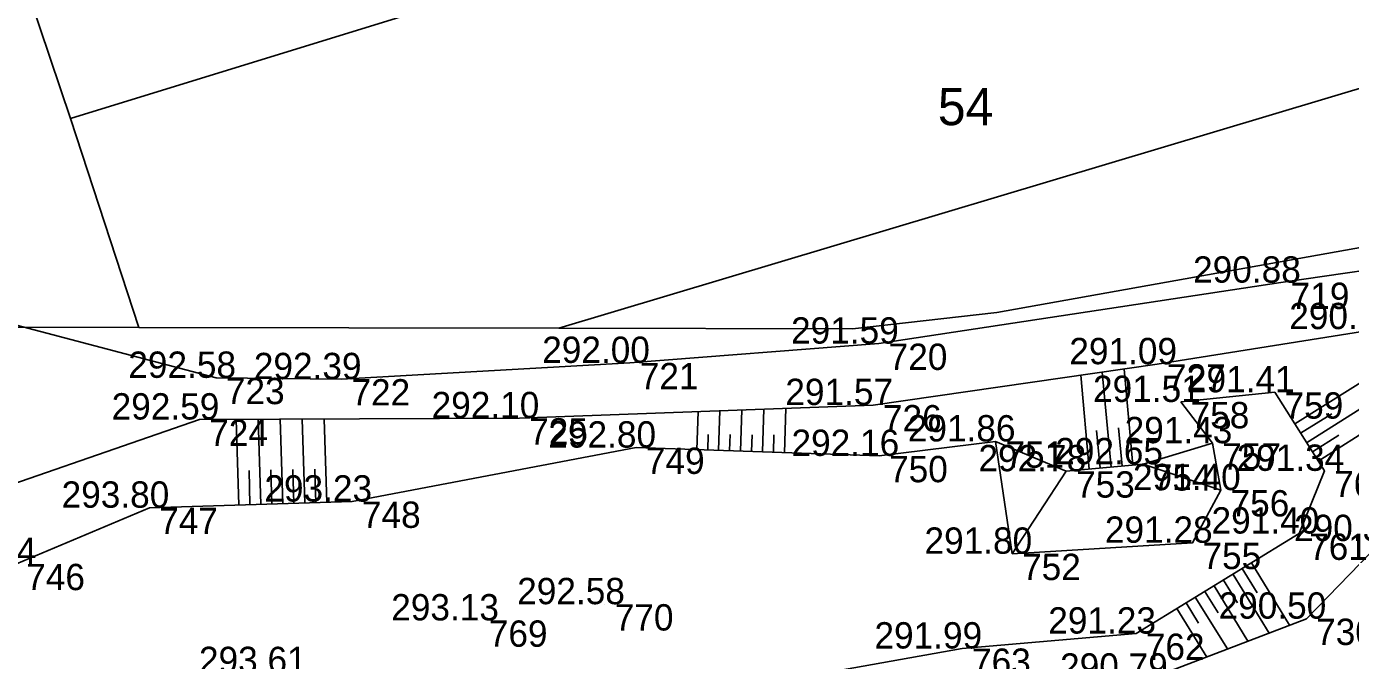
# Model space of a CAD drawing. Extents: x -599970 to -599524, y -1154772 to -1154457.
# Drawn here: x -599732.99 to -599702.82, y -1154607.5 to -1154593.05 of the extents above; entities that cross this region are included whole.
import ezdxf

# ---------------------------------------------------------------- set-up
doc = ezdxf.new("R2010")
doc.units = 0
for name, color, linetype in [('Z-KATASTRALNI MAPA', 7, 'Continuous'), ('Z-PLOT DRATENY', 7, 'Continuous'), ('Z-PODROBNE BODY', 7, 'Continuous'), ('Z-PODROBNE BODY-CISLO', 7, 'Continuous'), ('Z-PODROBNE BODY-VYSKA', 7, 'Continuous'), ('Z-SRAFOVANI SVAHU', 7, 'Continuous'), ('Z-TERENNI HRANY PATY', 7, 'Continuous')]:
    doc.layers.add(name, color=color, linetype=linetype)

msp = doc.modelspace()

# ---------------------------------------------------------------- linework, layer by layer
at = {"layer": 'Z-KATASTRALNI MAPA'}
for p, q in [((-599696.79, -1154584.29), (-599731.99, -1154595.15)), ((-599731.99, -1154595.15), (-599733.83, -1154589.64)), ((-599694.67, -1154592.08), (-599720.86, -1154599.93)), ((-599730.43, -1154599.91), (-599731.99, -1154595.15)), ((-599720.86, -1154599.93), (-599730.43, -1154599.91))]:
    msp.add_line(p, q, dxfattribs=at)
for points in [[(-599693.47, -1154596.46), (-599697.17, -1154597.32), (-599702, -1154597.98), (-599710.88, -1154599.57), (-599714.17, -1154599.94), (-599720.86, -1154599.93)], [(-599730.43, -1154599.91), (-599736.76, -1154599.9), (-599740.19, -1154600.9), (-599741.29, -1154597.51)]]:
    msp.add_lwpolyline(points, dxfattribs=at)
at = {"layer": 'Z-PLOT DRATENY'}
msp.add_lwpolyline([(-599741.2, -1154597.57), (-599735.3, -1154599.31), (-599728.67, -1154601.06), (-599725.81, -1154601.09), (-599719.24, -1154600.72), (-599713.57, -1154600.28), (-599704.41, -1154598.89), (-599697.5, -1154597.88)], dxfattribs=at)
at = {"layer": 'Z-PODROBNE BODY'}
for p, q in [((-599704.41, -1154598.89), (-599704.41, -1154598.89)), ((-599713.57, -1154600.28), (-599713.57, -1154600.28)), ((-599719.24, -1154600.72), (-599719.24, -1154600.72)), ((-599707.23, -1154600.75), (-599707.23, -1154600.75)), ((-599728.67, -1154601.06), (-599728.67, -1154601.06)), ((-599725.81, -1154601.09), (-599725.81, -1154601.09)), ((-599704.55, -1154601.39), (-599704.55, -1154601.39)), ((-599713.7, -1154601.68), (-599713.7, -1154601.68)), ((-599706.69, -1154601.61), (-599706.69, -1154601.61)), ((-599729.05, -1154602.01), (-599729.05, -1154602.01)), ((-599721.76, -1154601.98), (-599721.76, -1154601.98)), ((-599719.1, -1154602.65), (-599719.1, -1154602.65)), ((-599710.91, -1154602.51), (-599710.91, -1154602.51)), ((-599705.97, -1154602.55), (-599705.97, -1154602.55)), ((-599713.56, -1154602.84), (-599713.56, -1154602.84)), ((-599707.55, -1154603.03), (-599707.55, -1154603.03)), ((-599709.3, -1154603.19), (-599709.3, -1154603.19)), ((-599703.42, -1154603.18), (-599703.42, -1154603.18)), ((-599705.78, -1154603.62), (-599705.78, -1154603.62)), ((-599725.57, -1154603.88), (-599725.57, -1154603.88)), ((-599730.19, -1154604.02), (-599730.19, -1154604.02)), ((-599706.42, -1154604.82), (-599706.42, -1154604.82)), ((-599703.99, -1154604.61), (-599703.99, -1154604.61)), ((-599710.53, -1154605.07), (-599710.53, -1154605.07)), ((-599719.81, -1154606.22), (-599719.81, -1154606.22)), ((-599722.68, -1154606.59), (-599722.68, -1154606.59)), ((-599703.83, -1154606.55), (-599703.83, -1154606.55)), ((-599707.71, -1154606.89), (-599707.71, -1154606.89)), ((-599711.67, -1154607.23), (-599711.67, -1154607.23))]:
    msp.add_line(p, q, dxfattribs=at)
at = {"layer": 'Z-SRAFOVANI SVAHU'}
for points in [[(-599708.28, -1154603.1), (-599708.48, -1154600.93)], [(-599707.78, -1154603.05), (-599707.98, -1154600.86)], [(-599704.09, -1154602.11), (-599702.2, -1154600.92)], [(-599708.78, -1154603.14), (-599708.97, -1154601)], [(-599703.83, -1154602.54), (-599702.18, -1154601.5)], [(-599717.72, -1154602.7), (-599717.69, -1154601.83)], [(-599717.22, -1154602.71), (-599717.19, -1154601.81)], [(-599716.72, -1154602.73), (-599716.69, -1154601.79)], [(-599716.22, -1154602.75), (-599716.19, -1154601.77)], [(-599715.72, -1154602.77), (-599715.69, -1154601.75)], [(-599703.96, -1154602.32), (-599703.25, -1154601.88)], [(-599728.15, -1154603.96), (-599728.21, -1154602.01)], [(-599727.65, -1154603.94), (-599727.71, -1154602)], [(-599727.15, -1154603.93), (-599727.21, -1154602)], [(-599726.65, -1154603.91), (-599726.71, -1154602)], [(-599726.15, -1154603.9), (-599726.21, -1154602)], [(-599703.56, -1154602.96), (-599702.17, -1154602.08)], [(-599717.47, -1154602.71), (-599717.46, -1154602.35)], [(-599716.97, -1154602.72), (-599716.96, -1154602.35)], [(-599716.47, -1154602.74), (-599716.46, -1154602.36)], [(-599715.97, -1154602.76), (-599715.96, -1154602.36)], [(-599708.53, -1154603.12), (-599708.61, -1154602.26)], [(-599708.03, -1154603.07), (-599708.11, -1154602.2)], [(-599703.69, -1154602.75), (-599703.09, -1154602.37)], [(-599727.9, -1154603.95), (-599727.92, -1154603.17)], [(-599727.4, -1154603.94), (-599727.42, -1154603.16)], [(-599726.9, -1154603.92), (-599726.92, -1154603.15)], [(-599726.4, -1154603.91), (-599726.42, -1154603.14)], [(-599705.29, -1154605.41), (-599704.95, -1154605.96)], [(-599705.08, -1154605.28), (-599704.21, -1154606.7)], [(-599705.93, -1154605.8), (-599705.16, -1154607.06)], [(-599705.72, -1154605.67), (-599705.4, -1154606.19)], [(-599705.5, -1154605.54), (-599704.68, -1154606.88)], [(-599706.36, -1154606.06), (-599705.63, -1154607.24)], [(-599706.14, -1154605.93), (-599705.84, -1154606.42)], [(-599706.78, -1154606.32), (-599706.1, -1154607.43)], [(-599706.57, -1154606.19), (-599706.29, -1154606.65)]]:
    msp.add_lwpolyline(points, dxfattribs=at)
at = {"layer": 'Z-TERENNI HRANY PATY'}
for points in [[(-599729.05, -1154602.01), (-599721.76, -1154601.98), (-599713.7, -1154601.68), (-599707.23, -1154600.75), (-599702.22, -1154599.95), (-599702.11, -1154604.78), (-599703.83, -1154606.55), (-599707.44, -1154607.94), (-599715.66, -1154610.06), (-599723.72, -1154611.89), (-599730.02, -1154613.49), (-599734.59, -1154613.85), (-599735.4, -1154613.47), (-599737.38, -1154610.51), (-599738.93, -1154607.87), (-599737.97, -1154605.84), (-599735.06, -1154604.09), (-599729.05, -1154602.01)], [(-599706.69, -1154601.61), (-599704.55, -1154601.39), (-599703.42, -1154603.18), (-599703.99, -1154604.61), (-599707.71, -1154606.89), (-599711.67, -1154607.23), (-599718.57, -1154608.46), (-599724.85, -1154610.8), (-599730.76, -1154612.67), (-599734.46, -1154612.65)], [(-599710.91, -1154602.51), (-599710.53, -1154605.07), (-599706.42, -1154604.82), (-599705.78, -1154603.62), (-599705.97, -1154602.55), (-599706.69, -1154601.61)], [(-599734.46, -1154612.65), (-599734.67, -1154611.2), (-599735.18, -1154609.79), (-599737.16, -1154608.3), (-599736.95, -1154607.23), (-599733.22, -1154605.3), (-599730.19, -1154604.02), (-599725.57, -1154603.88), (-599719.1, -1154602.65), (-599713.56, -1154602.84), (-599710.91, -1154602.51)], [(-599710.91, -1154602.51), (-599709.3, -1154603.19), (-599710.53, -1154605.07)], [(-599705.97, -1154602.55), (-599707.55, -1154603.03), (-599705.78, -1154603.62)], [(-599709.3, -1154603.19), (-599707.55, -1154603.03)]]:
    msp.add_lwpolyline(points, dxfattribs=at)

# ---------------------------------------------------------------- texts
at = {"layer": 'Z-KATASTRALNI MAPA'}
msp.add_text('54', height=0.85, dxfattribs=at).set_placement((-599712.226, -1154595.3))
at = {"layer": 'Z-PODROBNE BODY-CISLO'}
for s, p in [(' 719', (-599704.41, -1154599.49)), (' 720', (-599713.57, -1154600.88)), (' 721', (-599719.24, -1154601.32)), (' 727', (-599707.23, -1154601.35)), (' 723', (-599728.67, -1154601.66)), (' 722', (-599725.81, -1154601.69)), (' 759', (-599704.55, -1154601.99)), (' 726', (-599713.7, -1154602.28)), (' 758', (-599706.69, -1154602.21)), (' 724', (-599729.05, -1154602.61)), (' 725', (-599721.76, -1154602.58)), (' 749', (-599719.1, -1154603.25)), (' 751', (-599710.91, -1154603.11)), (' 757', (-599705.97, -1154603.15)), (' 750', (-599713.56, -1154603.44)), (' 754', (-599707.55, -1154603.63)), (' 753', (-599709.3, -1154603.79)), (' 760', (-599703.42, -1154603.78)), (' 756', (-599705.78, -1154604.22)), (' 748', (-599725.57, -1154604.48)), (' 747', (-599730.19, -1154604.62)), (' 761', (-599703.99, -1154605.21)), (' 755', (-599706.42, -1154605.42)), (' 752', (-599710.53, -1154605.67)), (' 746', (-599733.22, -1154605.9)), (' 770', (-599719.81, -1154606.82)), (' 769', (-599722.68, -1154607.19)), (' 730', (-599703.83, -1154607.15)), (' 762', (-599707.71, -1154607.49)), (' 763', (-599711.67, -1154607.83))]:
    msp.add_text(s, height=0.6, dxfattribs=at).set_placement(p)
at = {"layer": 'Z-PODROBNE BODY-VYSKA'}
for s, p in [('290.88 ', (-599706.41, -1154598.89)), ('290.65 ', (-599704.22, -1154599.95)), ('291.59 ', (-599715.57, -1154600.28)), ('292.00 ', (-599721.24, -1154600.72)), ('291.09 ', (-599709.23, -1154600.75)), ('292.58 ', (-599730.67, -1154601.06)), ('292.39 ', (-599727.81, -1154601.09)), ('291.41 ', (-599706.55, -1154601.39)), ('291.57 ', (-599715.7, -1154601.68)), ('291.51 ', (-599708.69, -1154601.61)), ('292.59 ', (-599731.05, -1154602.01)), ('292.10 ', (-599723.76, -1154601.98)), ('292.80 ', (-599721.1, -1154602.65)), ('291.86 ', (-599712.91, -1154602.51)), ('291.43 ', (-599707.97, -1154602.55)), ('292.16 ', (-599715.56, -1154602.84)), ('292.65 ', (-599709.55, -1154603.03)), ('292.78 ', (-599711.3, -1154603.19)), ('291.34 ', (-599705.42, -1154603.18)), ('291.40 ', (-599707.78, -1154603.62)), ('293.23 ', (-599727.57, -1154603.88)), ('293.80 ', (-599732.19, -1154604.02)), ('291.28 ', (-599708.42, -1154604.82)), ('291.40 ', (-599705.99, -1154604.61)), ('290.37 ', (-599704.11, -1154604.78)), ('291.80 ', (-599712.53, -1154605.07)), ('293.84 ', (-599735.22, -1154605.3)), ('292.58 ', (-599721.81, -1154606.22)), ('293.13 ', (-599724.68, -1154606.59)), ('290.50 ', (-599705.83, -1154606.55)), ('291.23 ', (-599709.71, -1154606.89)), ('291.99 ', (-599713.67, -1154607.23)), ('293.61 ', (-599729.06, -1154607.79)), ('290.79 ', (-599709.44, -1154607.94))]:
    msp.add_text(s, height=0.6, dxfattribs=at).set_placement(p)

doc.saveas('drawing.dxf')
